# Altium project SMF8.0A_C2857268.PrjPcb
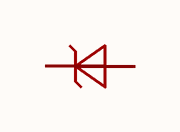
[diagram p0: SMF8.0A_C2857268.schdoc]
1 sheet, 1 parts. Net scope: global (net labels, ports and power ports of the same name join across sheets).

## Sheet SMF8.0A_C2857268.schdoc
size 127 x 101 mm

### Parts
D?  smf8.0a_c2857268  [SOD-123FL_L2.7-W1.8-LS3.7-RD]  (value not drawn)

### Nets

Not connected (* = marked no-connect by the designer): D? 1 2

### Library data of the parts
D? = smf8.0a_c2857268: 极性:单向;反向截止电压(Vrwm):8V;钳位电压:13.6V;峰值脉冲电流(Ipp):14.7A;峰值脉冲功率(Ppp):200W@10/1000us;击穿电压(VBR):8.89V;; Manufacturer: JSMSEMI(杰盛微); AddInBom: yes; ModelId: 86f9151e155e4fe2af0c4f2e0a80302e; ModelName: SOD-123FL_L2.8-W1.8-H1.1-LS3.6; ModelTransform: 141.732,70.866,0,180,0,0,0,0,0; Polarity: 单向; Reverse Stand-Off Voltage (Vrwm): 8V; Clamping Voltage: 13.6V; Peak Pulse Current (Ipp): 14.7A; Voltage - Breakdown: 8.89V; Reverse Leakage Current (Ir): 20uA; Number of Channels: 单路; Type: TVS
